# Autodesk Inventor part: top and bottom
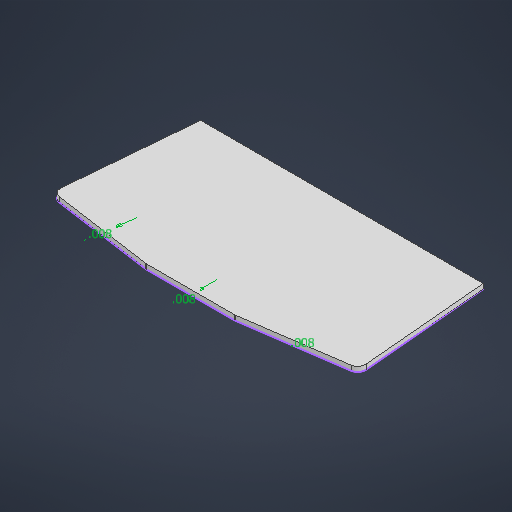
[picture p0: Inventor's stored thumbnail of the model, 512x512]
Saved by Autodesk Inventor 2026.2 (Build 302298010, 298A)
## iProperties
Created: 2026-08
Part Number: top and bottom
Material: Generic
Document SubType Name: Modeling
Designer: cpEwe
Density: 1 g/cm^3
Appearance: Default
Author: cpEwe
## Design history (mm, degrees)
sketch "Sketch1"
  geometry: L1 (27.887, -46.263)-(27.887, -46.264); L2 (-28.018, -44.358)-(-28.018, 50.642); L3 (-28.018, 50.642)-(25.982, 50.642); L4 (27.524, 52.547)-(-29.56, 52.547); L5 (25.982, -44.358)-(-28.018, -44.358); L6 (-29.923, -46.263)-(27.887, -46.263); L7 (-29.923, 46.132)-(-29.923, -44.358); L8 (-29.923, -46.263)-(-29.923, -46.264); L9 (-29.923, -46.264)-(-44.916, -46.263); L10 (-79.86, -44.358)-(-29.923, -44.358); L11 (-44.916, -46.263)-(-93.243, -46.263); L12 (-93.243, -46.263)-(-100.576, 37.549); L13 (-96.238, 43.02)-(-30.283, 52.496); L14 (-29.923, 46.132)-(-98.552, 36.273); L15 (-98.552, 36.273)-(-92.512, -32.765); L16 (27.887, -46.264)-(42.879, -46.263); L17 (77.824, -44.358)-(40.587, -44.358); L18 (27.887, -31.658)-(27.887, 46.132); L19 (25.982, 50.642)-(25.982, -44.358); L20 (42.879, -46.263)-(91.207, -46.263); L21 (91.207, -46.263)-(98.539, 37.549); L22 (94.201, 43.02)-(28.246, 52.496); L23 (27.887, 46.132)-(96.515, 36.273); L24 (96.515, 36.273)-(90.475, -32.765); L25 (96.3, 36.102)-(28.087, 45.901); L26 (28.087, 45.901)-(28.087, -31.658); L27 (40.587, -44.158)-(77.824, -44.158); L28 (90.276, -32.747)-(96.3, 36.102); L29 (25.782, 50.442)-(-27.818, 50.442); L30 (-27.818, 50.442)-(-27.818, -44.158); L31 (-27.818, -44.158)-(25.782, -44.158); L32 (25.782, -44.158)-(25.782, 50.442); L33 (-98.336, 36.102)-(-92.313, -32.747); L34 (-79.86, -44.158)-(-30.123, -44.158); L35 (-30.123, -44.158)-(-30.123, 45.901); L36 (-30.123, 45.901)-(-98.336, 36.102); A1 r 5.08 centre (-29.56, 47.467) between (-29.56, 52.547) and (-30.283, 52.496); A2 r 12.7 centre (-79.86, -31.658) between (-92.512, -32.765) and (-79.86, -44.358); A3 r 5.08 centre (-95.515, 37.992) between (-96.238, 43.02) and (-100.576, 37.549); A4 r 12.7 centre (40.587, -31.658) between (27.887, -31.658) and (40.587, -44.358); A5 r 5.08 centre (27.524, 47.467) between (28.246, 52.496) and (27.524, 52.547); A6 r 12.7 centre (77.824, -31.658) between (77.824, -44.358) and (90.475, -32.765); A7 r 5.08 centre (93.479, 37.992) between (98.539, 37.549) and (94.201, 43.02); A8 r 12.5 centre (40.587, -31.658) between (28.087, -31.658) and (40.587, -44.158); A9 r 12.5 centre (77.824, -31.658) between (77.824, -44.158) and (90.276, -32.747); A10 r 12.5 centre (-79.86, -31.658) between (-92.313, -32.747) and (-79.86, -44.158); 2 further points
  constraints: 72 end point, 20 point on circle, 10 centre point, 12 other
  dimensions: "d4" = 0.2 distance between parallel lines of L23 L25; "d5" = 0.2 distance between parallel lines of L3 L29; "d6" = 0.2 distance between parallel lines of L14 L36
extrude "Extrusion1" new body sketch "Sketch1" distance "d0" = 3.175; taper "d1" = 0 deg
extrude "Extrusion2" join sketch "Sketch1" distance "d2" = 1.905; taper "d3" = 0 deg
chamfer "Chamfer1" distance "d7" = 65.0875; stored, may be unused: second distance "d8" = 1.5875, angle "d9" = 45 deg
chamfer "Chamfer2" distance "d10" = 65.0875; stored, may be unused: second distance "d11" = 1.5875, angle "d12" = 45 deg
body "Solid1"
